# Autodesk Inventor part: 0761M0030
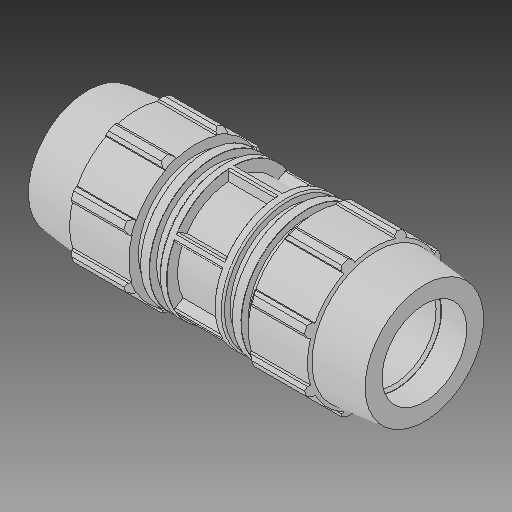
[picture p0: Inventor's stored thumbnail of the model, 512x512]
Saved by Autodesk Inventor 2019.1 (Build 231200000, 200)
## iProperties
Created: 2017-02
Part Number: 0761M0030
Material: Generic
Description: PLASSON REPAIR COUPLER 3'' - 3''
Document SubType Name: Modeling
Designer: KIM
Mass: 2544.89 g
Surface Area: 2949.22 cm^2
Volume: 2544.89 cm^3
Density: 1 g/cm^3
Appearance: Default
Author: KIM
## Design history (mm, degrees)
derived "0761M.ipt"
feature "Solid1::0761M.ipt"
tag "TaggingFeature1"
body "Solid1"
other parameters: "d1" = 352.806, "d2" = 88.7, "d4" = 29.4005, "d5" = 50.40086, "d7" = 151.892, "d8" = 113.919, "d9" = 50.40086, "d11" = 9.35567, "d12" = 121.5136, "d13" = 120 deg, "d14" = 124.18, "d15" = 6 deg, "d16" = 136.7028, "d19" = 35 deg, "d20" = 17.5 deg, "d21" = 141.25956, "d23" = 0, "d25" = 360 deg, "d27" = 3.03784, "d33" = 0.2, "d34" = 7.5946, "d36" = 0, "d37" = 1.774, "d38" = 1.774, "d40" = 360 deg, "d42" = 63.50508, "d43" = 4.55676, "d46" = 2.661, "d50" = 9.77041, "d51" = 121.5136, "d52" = 9.77041, "d_" = 88.7, "E_" = 151.892, "H_" = 352.806, "l_" = 160.02, "d49" = 28.89649
